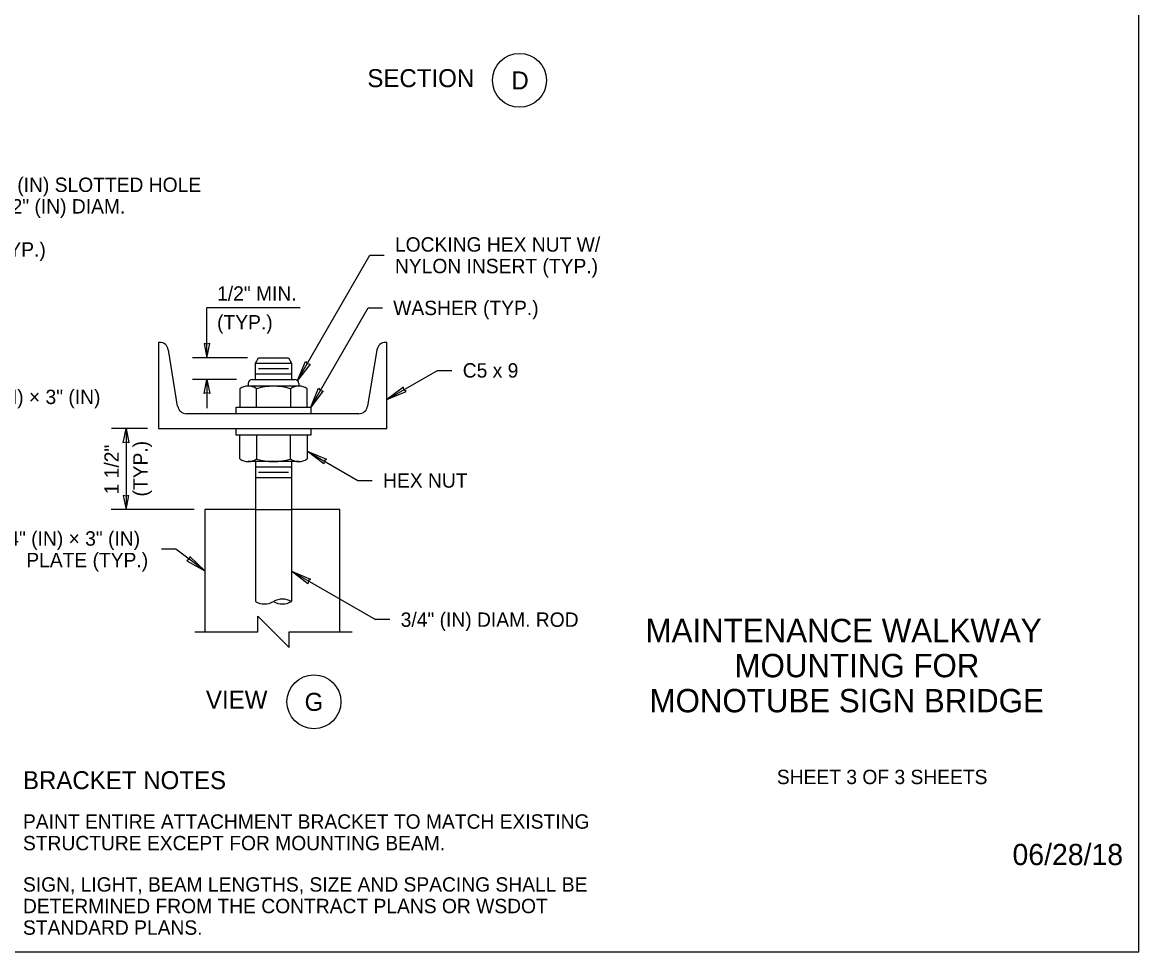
# Model space of a CAD drawing. Extents: x 99862 to 103151, y 100000 to 108076.
# Drawn here: x 101910 to 103151, y 106000 to 107033 of the extents above; entities that cross this region are included whole.
import ezdxf

# ---------------------------------------------------------------- set-up
doc = ezdxf.new("R2010")
doc.units = 0
for name, color, linetype in [('Level 1', 7, 'Continuous'), ('Level 15', 7, 'Continuous'), ('Level 20', 7, 'Continuous'), ('Level 21', 7, 'Continuous'), ('Level 3', 7, 'Continuous'), ('Level 36', 7, 'Continuous'), ('Level 62', 7, 'Continuous'), ('Level 9', 7, 'Continuous')]:
    doc.layers.add(name, color=color, linetype=linetype)

msp = doc.modelspace()

# ---------------------------------------------------------------- linework, layer by layer
at = {"layer": 'Level 1'}
msp.add_lwpolyline([(99862, 105999.5), (103151, 105999.5), (103151, 108075.5), (99862, 108075.5)], close=True, dxfattribs=at)
at = {"layer": 'Level 15'}
for p, q in [((102215.5, 106634.9), (102295.9, 106774.3)), ((102295.9, 106774.3), (102311.9, 106774.3)), ((102114.8, 106660.3), (102114.8, 106715.7)), ((102218.5, 106715.7), (102114.8, 106715.7)), ((102230.2, 106605.2), (102294, 106715.7)), ((102294, 106715.7), (102310, 106715.7)), ((102160.1, 106660.3), (102098.8, 106660.3)), ((102315, 106613.7), (102371.3, 106646.2)), ((102371.3, 106646.2), (102387.3, 106646.2)), ((102147.5, 106636.2), (102098.8, 106636.2)), ((102114.8, 106636.2), (102114.8, 106604.2)), ((102048.8, 106581.4), (102008.8, 106581.4)), ((102024.8, 106581.4), (102024.8, 106491.3)), ((102226.4, 106556.2), (102282.7, 106523.7)), ((102282.7, 106523.7), (102298.7, 106523.7)), ((102100.5, 106491.3), (102008.2, 106491.3)), ((102080.2, 106447.2), (102064.2, 106447.2)), ((102112.5, 106423.3), (102080.2, 106447.2)), ((102208.8, 106422.8), (102302.3, 106368.9)), ((102318.3, 106368.9), (102302.3, 106368.9))]:
    msp.add_line(p, q, dxfattribs=at)
for points in [[(102215.5, 106634.9), (102224.3, 106656.2), (102226.3, 106653.7), (102229.5, 106653.2)], [(102230.2, 106605.2), (102239, 106626.4), (102241.1, 106624), (102244.2, 106623.4)], [(102315, 106613.7), (102336.2, 106622.6), (102333.8, 106624.6), (102333.3, 106627.7)], [(102226.4, 106556.2), (102247.7, 106547.4), (102245.3, 106545.3), (102244.7, 106542.2)], [(102112.5, 106423.3), (102095.9, 106439.3), (102095, 106436.3), (102092.4, 106434.5)], [(102208.8, 106422.8), (102230.1, 106414), (102227.7, 106411.9), (102227.1, 106408.8)]]:
    msp.add_lwpolyline(points, close=True, dxfattribs=at)
msp.add_lwpolyline([(102101.4, 106355.3), (102171.4, 106355.3), (102171.4, 106372.7), (102206.3, 106337.9), (102206.3, 106355.3), (102276.3, 106355.3)], dxfattribs=at)
for centre, start, end in [((102178.8, 106406.3), 240, 300), ((102198.8, 106371.7), 60, 120), ((102198.8, 106406.3), 240, 300)]:
    msp.add_arc(centre, 20, start, end, dxfattribs=at)
at = {"layer": 'Level 3'}
for p, q in [((102082.2, 106606.3), (102071.9, 106669.1)), ((102172.1, 106660.3), (102205.4, 106660.3)), ((102303.9, 106669.1), (102293.5, 106606.3)), ((102168.8, 106654.4), (102208.8, 106654.4)), ((102172.1, 106648.4), (102205.4, 106648.4)), ((102165.3, 106636.2), (102212.4, 106636.2)), ((102168.8, 106642.5), (102208.8, 106642.5)), ((102151.3, 106625.7), (102151.3, 106605.2)), ((102217, 106628.6), (102160.6, 106628.6)), ((102160.7, 106631.6), (102160.7, 106628.6)), ((102170.1, 106605.2), (102170.1, 106625.7)), ((102207.6, 106625.7), (102207.6, 106605.2)), ((102217, 106631.6), (102217, 106628.7)), ((102226.4, 106605.2), (102226.4, 106625.7)), ((102283.7, 106598), (102092, 106598)), ((102060.8, 106581.4), (102315, 106581.4)), ((102151.3, 106547.8), (102151.3, 106574.2)), ((102170.1, 106574.2), (102170.1, 106547.8)), ((102207.6, 106547.8), (102207.6, 106574.2)), ((102226.4, 106574.2), (102226.4, 106547.8)), ((102217, 106544.8), (102160.6, 106544.8)), ((102168.8, 106544.8), (102168.8, 106389)), ((102168.8, 106538.8), (102208.8, 106538.8)), ((102208.8, 106544.8), (102208.8, 106389)), ((102168.8, 106526.9), (102208.8, 106526.9)), ((102172.1, 106532.9), (102205.4, 106532.9))]:
    msp.add_line(p, q, dxfattribs=at)
for points in [[(102062.3, 106677.2), (102060.8, 106677.2), (102060.8, 106581.4)], [(102315, 106581.4), (102315, 106677.2), (102313.4, 106677.2)], [(102168.8, 106636.2), (102168.8, 106654.4), (102172.1, 106660.3), (102205.4, 106660.3), (102208.8, 106654.4), (102208.8, 106642.5), (102208.8, 106636.2)], [(102168.8, 106491.3), (102112.5, 106491.3), (102112.5, 106355.3)], [(102262.6, 106355.3), (102262.6, 106491.3), (102208.8, 106491.3)]]:
    msp.add_lwpolyline(points, dxfattribs=at)
for points in [[(102114.8, 106660.3), (102117.9, 106676.1), (102114.8, 106675.3), (102111.8, 106676.1)], [(102114.8, 106636.2), (102117.9, 106620.5), (102114.8, 106621.2), (102111.8, 106620.5)], [(102147.3, 106605.2), (102230.4, 106605.2), (102230.4, 106598), (102147.3, 106598)], [(102024.8, 106581.4), (102027.9, 106565.7), (102024.8, 106566.4), (102021.7, 106565.7)], [(102147.3, 106581.4), (102230.4, 106581.4), (102230.4, 106574.2), (102147.3, 106574.2)], [(102024.8, 106491.3), (102027.9, 106507), (102024.8, 106506.3), (102021.7, 106507)]]:
    msp.add_lwpolyline(points, close=True, dxfattribs=at)
for centre, radius, start, end in [((102062.3, 106667.6), 9.7, 9.2424, 89.8703), ((102313.5, 106667.6), 9.7, 90.1297, 170.7576), ((102165.3, 106631.6), 4.61, 90, 180), ((102212.4, 106631.6), 4.61, 0, 90), ((102160.7, 106612.4), 16.3, 54.7356, 125.2644), ((102188.8, 106563.7), 64.9, 73.2213, 106.7787), ((102217, 106612.4), 16.3, 54.7356, 125.2644), ((102092.1, 106607.9), 9.96, 189.3215, 269.9494), ((102283.7, 106607.9), 9.96, 270.0506, 350.6785), ((102160.7, 106561.1), 16.3, 234.7356, 305.2644), ((102188.8, 106609.7), 64.9, 253.2213, 286.7787), ((102217, 106561.1), 16.3, 234.7356, 305.2644)]:
    msp.add_arc(centre, radius, start, end, dxfattribs=at)
at = {"layer": 'Level 36'}
msp.add_line((102168.8, 106491.3), (102208.8, 106491.3), dxfattribs=at)
at = {"layer": 'Level 9'}
for centre in [(102462.4, 106968.9), (102233.8, 106277.5)]:
    msp.add_circle(centre, 30, dxfattribs=at)

# ---------------------------------------------------------------- texts
at = {"layer": 'Level 15'}
msp.add_text('06/28/18', height=23.62, dxfattribs=at).set_placement((103010.7, 106095.8))
at = {"layer": 'Level 20'}
for s, height, p in [('SECTION', 20, (102293.2, 106961.3)), ('D', 20, (102453.4, 106958.8)), ('9/16" (IN) × 3/4" (IN) SLOTTED HOLE', 16, (101745.4, 106844.7)), ('(VERT.) FOR 1/2" (IN) DIAM.', 16, (101745.4, 106820.7)), ('LOCKING HEX NUT W/', 16, (102323.9, 106778.3)), ('BEAM BOLT (TYP.)', 16, (101745.4, 106772.7)), ('NYLON INSERT (TYP.)', 16, (102323.9, 106754.3)), ('1/2" MIN.', 16, (102126.1, 106723.7)), ('WASHER (TYP.)', 16, (102322, 106707.7)), ('(TYP.)', 16, (102126.1, 106691.7)), ('C5 x 9', 16, (102399.3, 106638.2)), ('3/8" (IN) × 4" (IN) × 3" (IN)', 16, (101746.5, 106608.7)), ('HEX NUT', 16, (102310.7, 106515.7)), ('3/8" (IN) × 4" (IN) × 3" (IN)', 16, (101790.6, 106451.2)), ('PLATE (TYP.)', 16, (101913.9, 106427.2)), ('3/4" (IN) DIAM. ROD', 16, (102330.3, 106360.9)), ('VIEW', 20, (102113.7, 106269.8)), ('G', 20, (102223.4, 106267.4)), ('BRACKET NOTES', 20, (101910.2, 106180.3)), ('PAINT ENTIRE ATTACHMENT BRACKET TO MATCH EXISTING', 16, (101910.2, 106136.3)), ('STRUCTURE EXCEPT FOR MOUNTING BEAM.', 16, (101910.2, 106112.3)), ('SIGN, LIGHT, BEAM LENGTHS, SIZE AND SPACING SHALL BE', 16, (101910.2, 106066.3)), ('DETERMINED FROM THE CONTRACT PLANS OR WSDOT', 16, (101910.2, 106042.3)), ('STANDARD PLANS.', 16, (101910.2, 106018.3))]:
    msp.add_text(s, height=height, dxfattribs=at).set_placement(p)
at = {"layer": 'Level 21'}
for s, p in [('1 1/2"', (102016.8, 106508.3)), ('(TYP.)', (102048.8, 106505.9))]:
    msp.add_text(s, height=16, rotation=90, dxfattribs=at).set_placement(p)
at = {"layer": 'Level 62'}
for s, height, p in [('MAINTENANCE WALKWAY', 26, (102602.6, 106343.8)), ('MOUNTING FOR', 26, (102701.5, 106304.8)), ('MONOTUBE SIGN BRIDGE', 26, (102607, 106265.8)), ('SHEET 3 OF 3 SHEETS', 16, (102748.6, 106185.9))]:
    msp.add_text(s, height=height, dxfattribs=at).set_placement(p)

doc.saveas('drawing.dxf')
